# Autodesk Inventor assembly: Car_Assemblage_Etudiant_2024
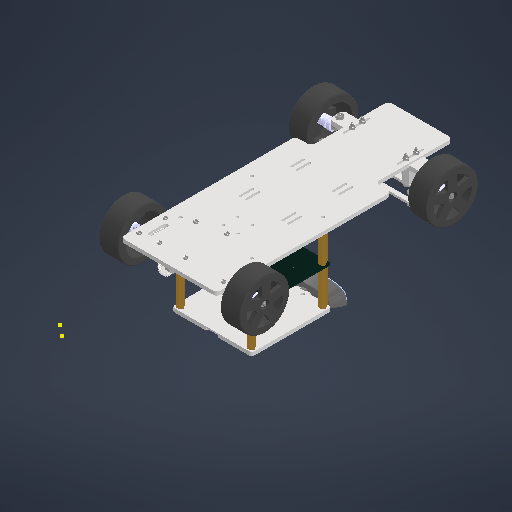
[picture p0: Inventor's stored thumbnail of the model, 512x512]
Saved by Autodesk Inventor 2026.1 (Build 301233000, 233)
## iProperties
Created: 2023-10
Part Number: Car_Assemblage_Etudiant_2024
Document SubType Name: Assembly
Designer: baince
Mass: 835.359 g
Surface Area: 2295.89 cm^2
Volume: 721.463 cm^3
Density: 1.15787 g/cm^3
Author: baince
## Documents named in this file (35)
- C:\Users\baince\Documents\Cours\Ateliers ROB\Autodesk Inventor\2025-2026\CAO Inventor Etudiant\Car_Assemblage_Etudiant_2024.iam
- C:\Users\baince\Documents\Cours\Ateliers ROB\Autodesk Inventor\2025-2026\CAO Inventor Etudiant\chassis.ipt
- C:\Users\baince\Documents\Cours\Ateliers ROB\Autodesk Inventor\2025-2026\CAO Inventor Etudiant\support_avant.ipt
- C:\Users\baince\Documents\Cours\Ateliers ROB\Autodesk Inventor\2025-2026\CAO Inventor Etudiant\support_arriere_gauche.ipt
- C:\Users\baince\Documents\Cours\Ateliers ROB\Autodesk Inventor\2025-2026\CAO Inventor Etudiant\moteur_brushless.ipt
- C:\Users\baince\Documents\Cours\Ateliers ROB\Autodesk Inventor\2025-2026\CAO Inventor Etudiant\adaptateur roue.ipt
- C:\Users\baince\Documents\Cours\Ateliers ROB\Autodesk Inventor\2025-2026\CAO Inventor Etudiant\adaptateur_brushless.ipt
- C:\Users\baince\Documents\Cours\Ateliers ROB\Autodesk Inventor\2025-2026\CAO Inventor Etudiant\roue.ipt
- C:\Users\baince\Documents\Cours\Ateliers ROB\Autodesk Inventor\2025-2026\CAO Inventor Etudiant\biellette_servo_moteur.ipt
- C:\Users\baince\Documents\Cours\Ateliers ROB\Autodesk Inventor\2025-2026\CAO Inventor Etudiant\support_servo_moteur.ipt
- C:\Users\baince\Documents\Cours\Ateliers ROB\Autodesk Inventor\2025-2026\CAO Inventor Etudiant\SUPPORT_MOTEUR_BRUSHLESS2.IPT
- C:\Users\baince\Documents\Cours\Ateliers ROB\Autodesk Inventor\2025-2026\CAO Inventor Etudiant\corps_servo_moteur.ipt
- C:\Users\baince\Documents\Cours\Ateliers ROB\Autodesk Inventor\2025-2026\CAO Inventor Etudiant\batterie.ipt
- C:\Users\baince\Documents\Cours\Ateliers ROB\Autodesk Inventor\2025-2026\CAO Inventor Etudiant\roulement_6_19.ipt
- C:\Users\baince\Documents\Cours\Ateliers ROB\Autodesk Inventor\2025-2026\CAO Inventor Etudiant\pignon_15_dents.ipt
- C:\Users\baince\Documents\Cours\Ateliers ROB\Autodesk Inventor\2025-2026\CAO Inventor Etudiant\pignon_32_dents.ipt
- C:\Users\baince\Documents\Cours\Ateliers ROB\Autodesk Inventor\2025-2026\CAO Inventor Etudiant\axe_taraude_m4.ipt
- C:\Users\baince\Documents\Cours\Ateliers ROB\Autodesk Inventor\2025-2026\CAO Inventor Etudiant\roulement_4_13.ipt
- C:\Users\baince\Documents\Cours\Ateliers ROB\Autodesk Inventor\2025-2026\CAO Inventor Etudiant\ISO 4032 - M4 - ISO.ipt
- C:\Users\baince\Documents\Cours\Ateliers ROB\Autodesk Inventor\2025-2026\CAO Inventor Etudiant\ANSI B18.16.3M - Property Class 5 and 10 - Metric M3 x 0.5 Type de métal.ipt
- C:\Users\baince\Documents\Cours\Ateliers ROB\Autodesk Inventor\2025-2026\CAO Inventor Etudiant\ANSI B18.3.1M - M3x0,5 x 30(1).ipt
- C:\Users\baince\Documents\Cours\Ateliers ROB\Autodesk Inventor\2025-2026\CAO Inventor Etudiant\ISO 4762 - M4 x 30ISO.ipt
- C:\Users\baince\Documents\Cours\Ateliers ROB\Autodesk Inventor\2025-2026\CAO Inventor Etudiant\ISO 7089 - 4 - 140 HV(1).ipt
- C:\Users\baince\Documents\Cours\Ateliers ROB\Autodesk Inventor\2025-2026\CAO Inventor Etudiant\ISO 4762 - M4 x 35ISO.ipt
- C:\Users\baince\Documents\Cours\Ateliers ROB\Autodesk Inventor\2025-2026\CAO Inventor Etudiant\SKF623.ipt
- C:\Users\baince\Documents\Cours\Ateliers ROB\Autodesk Inventor\2025-2026\CAO Inventor Etudiant\ISO 7089 - 6 - 140 HV(1).ipt
- C:\Users\baince\Documents\Cours\Ateliers ROB\Autodesk Inventor\2025-2026\CAO Inventor Etudiant\ANSI B18.3.1M - M3x0,5 x 35(1).ipt
- C:\Users\baince\Documents\Cours\Ateliers ROB\Autodesk Inventor\2025-2026\CAO Inventor Etudiant\ISO 7089 - 3 - 140 HV(1).ipt
- C:\Users\baince\Documents\Cours\Ateliers ROB\Autodesk Inventor\2025-2026\CAO Inventor Etudiant\EN ISO 7045 - M3 x 14 - 4.8 - Z(2).ipt
- C:\Users\baince\Documents\Cours\Ateliers ROB\Autodesk Inventor\2025-2026\CAO Inventor Etudiant\VisM3-16.ipt
- C:\Users\baince\Documents\Cours\Ateliers ROB\Autodesk Inventor\2025-2026\CAO Inventor Etudiant\support_avant_MIR2.ipt
- C:\Users\baince\Documents\Cours\Ateliers ROB\Autodesk Inventor\2025-2026\CAO Inventor Etudiant\ESSIEU_ARRIERE.IPT
- C:\Users\baince\Documents\Cours\Ateliers ROB\Autodesk Inventor\2025-2026\CAO Inventor Etudiant\barre_direction.ipt
- C:\Users\baince\Documents\Cours\Ateliers ROB\Autodesk Inventor\2025-2026\CAO Inventor Etudiant\pcb_assembly.iam
- C:\Users\baince\Documents\Cours\Ateliers ROB\Autodesk Inventor\2025-2026\CAO Inventor Etudiant\sensors_haut.iam
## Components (120 placed, 34 different names)
1. chassis:1 — Placage:1, Placage:5, Placage:19, Affleurement:1, Affleurement:2, Placage:21, Placage:22, Placage:23, Placage:26, Placage:27, Placage:28, Placage:66, Placage:68, Placage:70, Placage:72, Logement:57, Logement:58, Logement:59, Logement:60, Logement:61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
2. ESSIEU ARRIERE:1
3. support_avant:1 — Placage:1, Placage:3, Placage:4, Placage:5, Placage:7, Logement:30, Logement:84, Placage:87, Placage:89
4. moteur_brushless:1 — Placage:29, Placage:30, Placage:31, Logement:12
5. adaptateur roue:1 — Placage:43, Placage:44, Placage:45, Logement:18
6. adaptateur_brushless:1
7. roue:1 — Placage:42, Placage:46, Placage:47, Logement:39
8. roue:2 — Placage:41, Placage:48, Placage:49, Logement:41
9. roue:3 — Placage:40, Placage:50, Placage:51, Logement:37
10. roue:4 — Placage:43, Placage:44, Placage:45, Logement:35
11. support_arriere_gauche:2 — Placage:21, Placage:22, Placage:23, Placage:36, Placage:38, Logement:65, Logement:69
12. biellette_servo_moteur:1 — Placage:15, Placage:16, Placage:101, Placage:116
13. support_servo_moteur:1 — Placage:3, Placage:4, Placage:7, Placage:12, Placage:13, Placage:14, Logement:43, Logement:45, Logement:47, Logement:49
14. SUPPORT_MOTEUR_BRUSHLESS2:1 — Placage:26, Placage:27, Placage:28, Placage:32, Placage:33, Placage:34, Logement:66, Logement:70, Logement:73, Logement:74, Logement:75, Logement:76
15. corps_servo_moteur:1 — Placage:12, Placage:13, Placage:14, Placage:15, Placage:16
16. batterie:1 — Placage:19, Affleurement:1, Affleurement:2
17. roulement_6_19:1 — Logement:27
18. roulement_6_19:2 — Placage:36, Placage:38
19. adaptateur roue:2 — Placage:42, Placage:46, Placage:47
20. adaptateur roue:3 — Placage:41, Placage:48, Placage:49, Placage:115
21. adaptateur roue:4 — Placage:40, Placage:50, Placage:51, Logement:19
22. pignon_15_dents:1 — Logement:12, Tangente:1
23. pignon_32_dents:1 — Tangente:2
24. axe_taraude_m4:1 — Logement:25, Placage:63
25. roulement_4_13:1 — Logement:6, Placage:92, Placage:113
26. roulement_4_13:2 — Logement:3, Placage:114
27. roulement_4_13:3 — Logement:8, Placage:90
28. roulement_4_13:4 — Logement:10, Placage:109, Placage:110
29. ISO 4032 M4:1 — Logement:31
30. Ecrou hexagonal autofreiné - Acier Métrique Property Class 5 and 10 - Metric M3 x 0.5 Type de métal:1 — Logement:52
31. Vis à tête forgée - Métrique M3x0,5 x 30:1 — Logement:22, Placage:62
32. ISO 4762 M4 x 30:1 — Logement:2, Placage:111, Placage:112
33. ISO 4762 M4 x 30:2 — Logement:7, Placage:108, Placage:109
34. ISO 7089 4:1 — Logement:30, Logement:31
35. ISO 4762 M4 x 35:1 — Logement:83
36. ISO 4762 M4 x 35:2 — Logement:85
37. ISO 7089 4:2 — Logement:2, Logement:3
38. ISO 7089 4:3 — Logement:6, Logement:18
39. ISO 7089 4:4 — Logement:10, Logement:19
40. ISO 7089 4:5 — Logement:7, Logement:8
41. roulement_6_19:3 — Logement:25, Placage:81
42. SKF- roulements à une rangée de billes SKF623:1 — Logement:22, Logement:54
43. ISO 7089 6:1 — Logement:29, Placage:64, Placage:107
44. ISO 7089 6:2 — Logement:27
45. pignon_32_dents:2 — Placage:63, Placage:64, Tangente:1, Placage:81, Placage:107
46. pignon_15_dents:2 — Placage:62, Logement:29, Tangente:2
47. ISO 4032 M4:2 — Logement:32
48. ISO 4032 M4:3 — Logement:34
49. ISO 4032 M4:4 — Logement:36
50. ISO 4032 M4:5 — Logement:38
51. ISO 4032 M4:6 — Logement:40
52. ISO 7089 4:6 — Logement:34, Logement:35
53. ISO 7089 4:7 — Logement:36, Logement:37
54. ISO 7089 4:8 — Logement:38, Logement:39
55. ISO 7089 4:9 — Logement:40, Logement:41
56. ISO 7089 4:10 — Logement:32, Logement:96
57. Vis à tête forgée - Métrique M3x0,5 x 35:1 — Logement:42, Placage:69
58. Vis à tête forgée - Métrique M3x0,5 x 35:2 — Logement:44, Placage:71
59. Vis à tête forgée - Métrique M3x0,5 x 35:3 — Logement:48, Placage:65, Placage:76
60. Vis à tête forgée - Métrique M3x0,5 x 35:4 — Logement:46, Placage:67, Placage:79
61. Ecrou hexagonal autofreiné - Acier Métrique Property Class 5 and 10 - Metric M3 x 0.5 Type de métal:2 — Logement:50
62. Ecrou hexagonal autofreiné - Acier Métrique Property Class 5 and 10 - Metric M3 x 0.5 Type de métal:3 — Logement:51
63. Ecrou hexagonal autofreiné - Acier Métrique Property Class 5 and 10 - Metric M3 x 0.5 Type de métal:4 — Logement:53
64. ISO 7089 3:1 — Logement:44, Logement:45
65. ISO 7089 3:2 — Logement:46, Logement:47
66. ISO 7089 3:3 — Logement:52, Placage:71, Placage:72
67. ISO 7089 3:4 — Logement:53, Placage:65, Placage:66
68. ISO 7089 3:5 — Logement:48, Logement:49
69. ISO 7089 3:6 — Logement:54, Logement:55
70. ISO 7089 3:7 — Logement:50, Placage:69, Placage:70
71. ISO 7089 3:8 — Logement:42, Logement:43
72. ISO 7089 3:9 — Logement:51, Placage:67, Placage:68
73. ISO 7089 3:10 — Logement:55, Logement:56
74. ISO 7089 3:11 — Logement:56
75. NF EN ISO 7045 - Z M3 x 14 - 4.8 - Z:1 — Logement:60
76. NF EN ISO 7045 - Z M3 x 14 - 4.8 - Z:2 — Logement:59
77. NF EN ISO 7045 - Z M3 x 14 - 4.8 - Z:3 — Logement:58
78. NF EN ISO 7045 - Z M3 x 14 - 4.8 - Z:4 — Logement:57
79. NF EN ISO 7045 - Z M3 x 14 - 4.8 - Z:5 — Logement:61
80. NF EN ISO 7045 - Z M3 x 14 - 4.8 - Z:6 — Logement:62
81. NF EN ISO 7045 - Z M3 x 14 - 4.8 - Z:7 — Logement:63
82. NF EN ISO 7045 - Z M3 x 14 - 4.8 - Z:8 — Logement:64
83. Ecrou hexagonal autofreiné - Acier Métrique Property Class 5 and 10 - Metric M3 x 0.5 Type de métal:5 — Logement:65
84. Ecrou hexagonal autofreiné - Acier Métrique Property Class 5 and 10 - Metric M3 x 0.5 Type de métal:6
85. Ecrou hexagonal autofreiné - Acier Métrique Property Class 5 and 10 - Metric M3 x 0.5 Type de métal:7
86. Ecrou hexagonal autofreiné - Acier Métrique Property Class 5 and 10 - Metric M3 x 0.5 Type de métal:8 — Logement:66
87. Ecrou hexagonal autofreiné - Acier Métrique Property Class 5 and 10 - Metric M3 x 0.5 Type de métal:9 — Logement:75
88. Ecrou hexagonal autofreiné - Acier Métrique Property Class 5 and 10 - Metric M3 x 0.5 Type de métal:10 — Logement:69
89. Ecrou hexagonal autofreiné - Acier Métrique Property Class 5 and 10 - Metric M3 x 0.5 Type de métal:11 — Logement:70
90. Ecrou hexagonal autofreiné - Acier Métrique Property Class 5 and 10 - Metric M3 x 0.5 Type de métal:12 — Logement:73
91. Ecrou hexagonal autofreiné - Acier Métrique Property Class 5 and 10 - Metric M3 x 0.5 Type de métal:13
92. Ecrou hexagonal autofreiné - Acier Métrique Property Class 5 and 10 - Metric M3 x 0.5 Type de métal:14
93. Ecrou hexagonal autofreiné - Acier Métrique Property Class 5 and 10 - Metric M3 x 0.5 Type de métal:15 — Logement:74
94. Ecrou hexagonal autofreiné - Acier Métrique Property Class 5 and 10 - Metric M3 x 0.5 Type de métal:16 — Logement:76
95. NF EN ISO 7045 - Z M3 x 14 - 4.8 - Z:9 — Logement:77
96. NF EN ISO 7045 - Z M3 x 14 - 4.8 - Z:10 — Logement:78
97. NF EN ISO 7045 - Z M3 x 14 - 4.8 - Z:11 — Logement:80
98. NF EN ISO 7045 - Z M3 x 14 - 4.8 - Z:12 — Logement:79
99. VisM3-16:1 — Logement:88
100. VisM3-16:2 — Logement:89
101. Ecrou hexagonal autofreiné - Acier Métrique Property Class 5 and 10 - Metric M3 x 0.5 Type de métal:17 — Logement:87
102. Ecrou hexagonal autofreiné - Acier Métrique Property Class 5 and 10 - Metric M3 x 0.5 Type de métal:18
103. ISO 7089 3:13
104. ISO 7089 3:14 — Logement:87
105. ISO 7089 3:15 — Logement:89, Placage:100
106. ISO 7089 4:11 — Logement:83, Logement:84
107. ISO 7089 4:12 — Logement:85, Logement:95
108. ISO 7089 3:16 — Logement:88, Placage:99
109. support_avant_MIR2:1
110. barre_direction:1 — Placage:99, Placage:100, Placage:101, Placage:116
111. ISO 7089 4:13 — Placage:88
112. ISO 7089 4:14 — Placage:85
113. ISO 7089 4:15 — Placage:87
114. ISO 7089 4:16 — Placage:89
115. ISO 7089 4:17 — Placage:91, Placage:108, Placage:110
116. ISO 7089 4:18 — Placage:90, Placage:91
117. ISO 7089 4:19 — Placage:93, Placage:111, Placage:114
118. ISO 7089 4:20 — Placage:92, Placage:93, Placage:112, Placage:113
119. pcb_assembly:1 [sub-assembly] — Placage:102, Placage:103, Placage:104, Placage:105, Placage:106
120. sensors_haut:1 [sub-assembly] — Placage:105, Placage:106
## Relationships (151: Mate 80, Insert 67, Flush 2, Tangent 2)
- Placage:1 [Mate]: chassis:1 ↔ support_avant:1
- Placage:3 [Mate]: support_avant:1 ↔ support_servo_moteur:1
- Placage:4 [Mate]: support_avant:1 ↔ support_servo_moteur:1
- Placage:5 [Mate]: chassis:1 ↔ support_avant:1
- Placage:7 [Mate]: support_avant:1 ↔ support_servo_moteur:1
- Placage:12 [Mate]: support_servo_moteur:1 ↔ corps_servo_moteur:1
- Placage:13 [Mate]: support_servo_moteur:1 ↔ corps_servo_moteur:1
- Placage:14 [Mate]: support_servo_moteur:1 ↔ corps_servo_moteur:1
- Placage:15 [Mate]: biellette_servo_moteur:1 ↔ corps_servo_moteur:1
- Placage:16 [Mate]: biellette_servo_moteur:1 ↔ corps_servo_moteur:1
- Placage:19 [Mate]: chassis:1 ↔ batterie:1
- Affleurement:1 [Flush]: chassis:1 ↔ batterie:1
- Affleurement:2 [Flush]: chassis:1 ↔ batterie:1
- Placage:21 [Mate]: chassis:1 ↔ support_arriere_gauche:2
- Placage:22 [Mate]: chassis:1 ↔ support_arriere_gauche:2
- Placage:23 [Mate]: chassis:1 ↔ support_arriere_gauche:2
- Placage:26 [Mate]: chassis:1 ↔ SUPPORT_MOTEUR_BRUSHLESS2:1
- Placage:27 [Mate]: chassis:1 ↔ SUPPORT_MOTEUR_BRUSHLESS2:1
- Placage:28 [Mate]: chassis:1 ↔ SUPPORT_MOTEUR_BRUSHLESS2:1
- Placage:29 [Mate]: moteur_brushless:1
- Placage:30 [Mate]: moteur_brushless:1
- Placage:31 [Mate]: moteur_brushless:1
- Placage:32 [Mate]: SUPPORT_MOTEUR_BRUSHLESS2:1
- Placage:33 [Mate]: SUPPORT_MOTEUR_BRUSHLESS2:1
- Placage:34 [Mate]: SUPPORT_MOTEUR_BRUSHLESS2:1
- Placage:36 [Mate]: support_arriere_gauche:2 ↔ roulement_6_19:2
- Placage:38 [Mate]: support_arriere_gauche:2 ↔ roulement_6_19:2
- Placage:40 [Mate]: roue:3 ↔ adaptateur roue:4
- Placage:41 [Mate]: roue:2 ↔ adaptateur roue:3
- Placage:42 [Mate]: roue:1 ↔ adaptateur roue:2
- Placage:43 [Mate]: adaptateur roue:1 ↔ roue:4
- Placage:44 [Mate]: adaptateur roue:1 ↔ roue:4
- Placage:45 [Mate]: adaptateur roue:1 ↔ roue:4
- Placage:46 [Mate]: roue:1 ↔ adaptateur roue:2
- Placage:47 [Mate]: roue:1 ↔ adaptateur roue:2
- Placage:48 [Mate]: roue:2 ↔ adaptateur roue:3
- Placage:49 [Mate]: roue:2 ↔ adaptateur roue:3
- Placage:50 [Mate]: roue:3 ↔ adaptateur roue:4
- Placage:51 [Mate]: roue:3 ↔ adaptateur roue:4
- Logement:2 [Insert]: ISO 4762 M4 x 30:1 ↔ ISO 7089 4:2
- Logement:3 [Insert]: roulement_4_13:2 ↔ ISO 7089 4:2
- Logement:6 [Insert]: roulement_4_13:1 ↔ ISO 7089 4:3
- Logement:7 [Insert]: ISO 4762 M4 x 30:2 ↔ ISO 7089 4:5
- Logement:8 [Insert]: roulement_4_13:3 ↔ ISO 7089 4:5
- Logement:10 [Insert]: roulement_4_13:4 ↔ ISO 7089 4:4
- Logement:12 [Insert]: moteur_brushless:1 ↔ pignon_15_dents:1
- Logement:18 [Insert]: adaptateur roue:1 ↔ ISO 7089 4:3
- Logement:19 [Insert]: adaptateur roue:4 ↔ ISO 7089 4:4
- Logement:22 [Insert]: Vis à tête forgée - Métrique M3x0,5 x 30:1 ↔ SKF- roulements à une rangée de billes SKF623:1
- Logement:25 [Insert]: axe_taraude_m4:1 ↔ roulement_6_19:3
- Logement:27 [Insert]: roulement_6_19:1 ↔ ISO 7089 6:2
- Placage:62 [Mate]: Vis à tête forgée - Métrique M3x0,5 x 30:1 ↔ pignon_15_dents:2
- Logement:29 [Insert]: ISO 7089 6:1 ↔ pignon_15_dents:2
- Placage:63 [Mate]: axe_taraude_m4:1 ↔ pignon_32_dents:2
- Placage:64 [Mate]: ISO 7089 6:1 ↔ pignon_32_dents:2
- Tangente:1: pignon_15_dents:1 ↔ pignon_32_dents:2
- Tangente:2: pignon_32_dents:1 ↔ pignon_15_dents:2
- Logement:30 [Insert]: support_avant:1 ↔ ISO 7089 4:1
- Logement:31 [Insert]: ISO 4032 M4:1 ↔ ISO 7089 4:1
- Logement:32 [Insert]: ISO 4032 M4:2 ↔ ISO 7089 4:10
- Logement:34 [Insert]: ISO 4032 M4:3 ↔ ISO 7089 4:6
- Logement:35 [Insert]: roue:4 ↔ ISO 7089 4:6
- Logement:36 [Insert]: ISO 4032 M4:4 ↔ ISO 7089 4:7
- Logement:37 [Insert]: roue:3 ↔ ISO 7089 4:7
- Logement:38 [Insert]: ISO 4032 M4:5 ↔ ISO 7089 4:8
- Logement:39 [Insert]: roue:1 ↔ ISO 7089 4:8
- Logement:40 [Insert]: ISO 4032 M4:6 ↔ ISO 7089 4:9
- Logement:41 [Insert]: roue:2 ↔ ISO 7089 4:9
- Logement:42 [Insert]: Vis à tête forgée - Métrique M3x0,5 x 35:1 ↔ ISO 7089 3:8
- Logement:43 [Insert]: support_servo_moteur:1 ↔ ISO 7089 3:8
- Logement:44 [Insert]: Vis à tête forgée - Métrique M3x0,5 x 35:2 ↔ ISO 7089 3:1
- Logement:45 [Insert]: support_servo_moteur:1 ↔ ISO 7089 3:1
- Logement:46 [Insert]: Vis à tête forgée - Métrique M3x0,5 x 35:4 ↔ ISO 7089 3:2
- Logement:47 [Insert]: support_servo_moteur:1 ↔ ISO 7089 3:2
- Logement:48 [Insert]: Vis à tête forgée - Métrique M3x0,5 x 35:3 ↔ ISO 7089 3:5
- Logement:49 [Insert]: support_servo_moteur:1 ↔ ISO 7089 3:5
- Logement:50 [Insert]: Ecrou hexagonal autofreiné - Acier Métrique Property Class 5 and 10 - Metric M3 x 0.5 Type de métal:2 ↔ ISO 7089 3:7
- Logement:51 [Insert]: Ecrou hexagonal autofreiné - Acier Métrique Property Class 5 and 10 - Metric M3 x 0.5 Type de métal:3 ↔ ISO 7089 3:9
- Logement:52 [Insert]: Ecrou hexagonal autofreiné - Acier Métrique Property Class 5 and 10 - Metric M3 x 0.5 Type de métal:1 ↔ ISO 7089 3:3
- Logement:53 [Insert]: Ecrou hexagonal autofreiné - Acier Métrique Property Class 5 and 10 - Metric M3 x 0.5 Type de métal:4 ↔ ISO 7089 3:4
- Placage:65 [Mate]: Vis à tête forgée - Métrique M3x0,5 x 35:3 ↔ ISO 7089 3:4
- Placage:66 [Mate]: chassis:1 ↔ ISO 7089 3:4
- Placage:67 [Mate]: Vis à tête forgée - Métrique M3x0,5 x 35:4 ↔ ISO 7089 3:9
- Placage:68 [Mate]: chassis:1 ↔ ISO 7089 3:9
- Placage:69 [Mate]: Vis à tête forgée - Métrique M3x0,5 x 35:1 ↔ ISO 7089 3:7
- Placage:70 [Mate]: chassis:1 ↔ ISO 7089 3:7
- Placage:71 [Mate]: Vis à tête forgée - Métrique M3x0,5 x 35:2 ↔ ISO 7089 3:3
- Placage:72 [Mate]: chassis:1 ↔ ISO 7089 3:3
- Logement:54 [Insert]: SKF- roulements à une rangée de billes SKF623:1 ↔ ISO 7089 3:6
- Logement:55 [Insert]: ISO 7089 3:6 ↔ ISO 7089 3:10
- Logement:56 [Insert]: ISO 7089 3:10 ↔ ISO 7089 3:11
- Logement:57 [Insert]: chassis:1 ↔ NF EN ISO 7045 - Z M3 x 14 - 4.8 - Z:4
- Logement:58 [Insert]: chassis:1 ↔ NF EN ISO 7045 - Z M3 x 14 - 4.8 - Z:3
- Logement:59 [Insert]: chassis:1 ↔ NF EN ISO 7045 - Z M3 x 14 - 4.8 - Z:2
- Logement:60 [Insert]: chassis:1 ↔ NF EN ISO 7045 - Z M3 x 14 - 4.8 - Z:1
- Logement:61 [Insert]: chassis:1 ↔ NF EN ISO 7045 - Z M3 x 14 - 4.8 - Z:5
- Logement:62 [Insert]: chassis:1 ↔ NF EN ISO 7045 - Z M3 x 14 - 4.8 - Z:6
- Logement:63 [Insert]: chassis:1 ↔ NF EN ISO 7045 - Z M3 x 14 - 4.8 - Z:7
- Logement:64 [Insert]: chassis:1 ↔ NF EN ISO 7045 - Z M3 x 14 - 4.8 - Z:8
- Logement:65 [Insert]: support_arriere_gauche:2 ↔ Ecrou hexagonal autofreiné - Acier Métrique Property Class 5 and 10 - Metric M3 x 0.5 Type de métal:5
- Logement:66 [Insert]: SUPPORT_MOTEUR_BRUSHLESS2:1 ↔ Ecrou hexagonal autofreiné - Acier Métrique Property Class 5 and 10 - Metric M3 x 0.5 Type de métal:8
- Logement:69 [Insert]: support_arriere_gauche:2 ↔ Ecrou hexagonal autofreiné - Acier Métrique Property Class 5 and 10 - Metric M3 x 0.5 Type de métal:10
- Logement:70 [Insert]: SUPPORT_MOTEUR_BRUSHLESS2:1 ↔ Ecrou hexagonal autofreiné - Acier Métrique Property Class 5 and 10 - Metric M3 x 0.5 Type de métal:11
- Logement:73 [Insert]: SUPPORT_MOTEUR_BRUSHLESS2:1 ↔ Ecrou hexagonal autofreiné - Acier Métrique Property Class 5 and 10 - Metric M3 x 0.5 Type de métal:12
- Logement:74 [Insert]: SUPPORT_MOTEUR_BRUSHLESS2:1 ↔ Ecrou hexagonal autofreiné - Acier Métrique Property Class 5 and 10 - Metric M3 x 0.5 Type de métal:15
- Logement:75 [Insert]: SUPPORT_MOTEUR_BRUSHLESS2:1 ↔ Ecrou hexagonal autofreiné - Acier Métrique Property Class 5 and 10 - Metric M3 x 0.5 Type de métal:9
- Logement:76 [Insert]: SUPPORT_MOTEUR_BRUSHLESS2:1 ↔ Ecrou hexagonal autofreiné - Acier Métrique Property Class 5 and 10 - Metric M3 x 0.5 Type de métal:16
- Logement:77 [Insert]: NF EN ISO 7045 - Z M3 x 14 - 4.8 - Z:9
- Logement:78 [Insert]: NF EN ISO 7045 - Z M3 x 14 - 4.8 - Z:10
- Logement:79 [Insert]: NF EN ISO 7045 - Z M3 x 14 - 4.8 - Z:12
- Logement:80 [Insert]: NF EN ISO 7045 - Z M3 x 14 - 4.8 - Z:11
- Logement:83 [Insert]: ISO 4762 M4 x 35:1 ↔ ISO 7089 4:11
- Logement:84 [Insert]: support_avant:1 ↔ ISO 7089 4:11
- Logement:85 [Insert]: ISO 4762 M4 x 35:2 ↔ ISO 7089 4:12
- Logement:87 [Insert]: Ecrou hexagonal autofreiné - Acier Métrique Property Class 5 and 10 - Metric M3 x 0.5 Type de métal:17 ↔ ISO 7089 3:14
- Logement:88 [Insert]: VisM3-16:1 ↔ ISO 7089 3:16
- Logement:89 [Insert]: VisM3-16:2 ↔ ISO 7089 3:15
- Placage:74 [Mate]: chassis:1
- Placage:75 [Mate]: chassis:1
- Placage:76 [Mate]: Vis à tête forgée - Métrique M3x0,5 x 35:3
- Logement:95 [Insert]: ISO 7089 4:12
- Placage:79 [Mate]: Vis à tête forgée - Métrique M3x0,5 x 35:4
- Placage:80 [Mate]: chassis:1
- Logement:96 [Insert]: ISO 7089 4:10
- Placage:81 [Mate]: roulement_6_19:3 ↔ pignon_32_dents:2
- Placage:85 [Mate]: ISO 7089 4:14
- Placage:87 [Mate]: support_avant:1 ↔ ISO 7089 4:15
- Placage:88 [Mate]: ISO 7089 4:13
- Placage:89 [Mate]: support_avant:1 ↔ ISO 7089 4:16
- Placage:90 [Mate]: roulement_4_13:3 ↔ ISO 7089 4:18
- Placage:91 [Mate]: ISO 7089 4:17 ↔ ISO 7089 4:18
- Placage:92 [Mate]: roulement_4_13:1 ↔ ISO 7089 4:20
- Placage:93 [Mate]: ISO 7089 4:19 ↔ ISO 7089 4:20
- Placage:99 [Mate]: ISO 7089 3:16 ↔ barre_direction:1
- Placage:100 [Mate]: ISO 7089 3:15 ↔ barre_direction:1
- Placage:101 [Mate]: biellette_servo_moteur:1 ↔ barre_direction:1
- Placage:102 [Mate]: chassis:1 ↔ pcb_assembly:1
- Placage:103 [Mate]: chassis:1 ↔ pcb_assembly:1
- Placage:104 [Mate]: chassis:1 ↔ pcb_assembly:1
- Placage:105 [Mate]: pcb_assembly:1 ↔ sensors_haut:1
- Placage:106 [Mate]: pcb_assembly:1 ↔ sensors_haut:1
- Placage:107 [Mate]: ISO 7089 6:1 ↔ pignon_32_dents:2
- Placage:108 [Mate]: ISO 4762 M4 x 30:2 ↔ ISO 7089 4:17
- Placage:109 [Mate]: roulement_4_13:4 ↔ ISO 4762 M4 x 30:2
- Placage:110 [Mate]: roulement_4_13:4 ↔ ISO 7089 4:17
- Placage:111 [Mate]: ISO 4762 M4 x 30:1 ↔ ISO 7089 4:19
- Placage:112 [Mate]: ISO 4762 M4 x 30:1 ↔ ISO 7089 4:20
- Placage:113 [Mate]: roulement_4_13:1 ↔ ISO 7089 4:20
- Placage:114 [Mate]: roulement_4_13:2 ↔ ISO 7089 4:19
- Placage:115 [Mate]: adaptateur roue:3
- Placage:116 [Mate]: biellette_servo_moteur:1 ↔ barre_direction:1
## Named parameters: d185_d147 = 0
